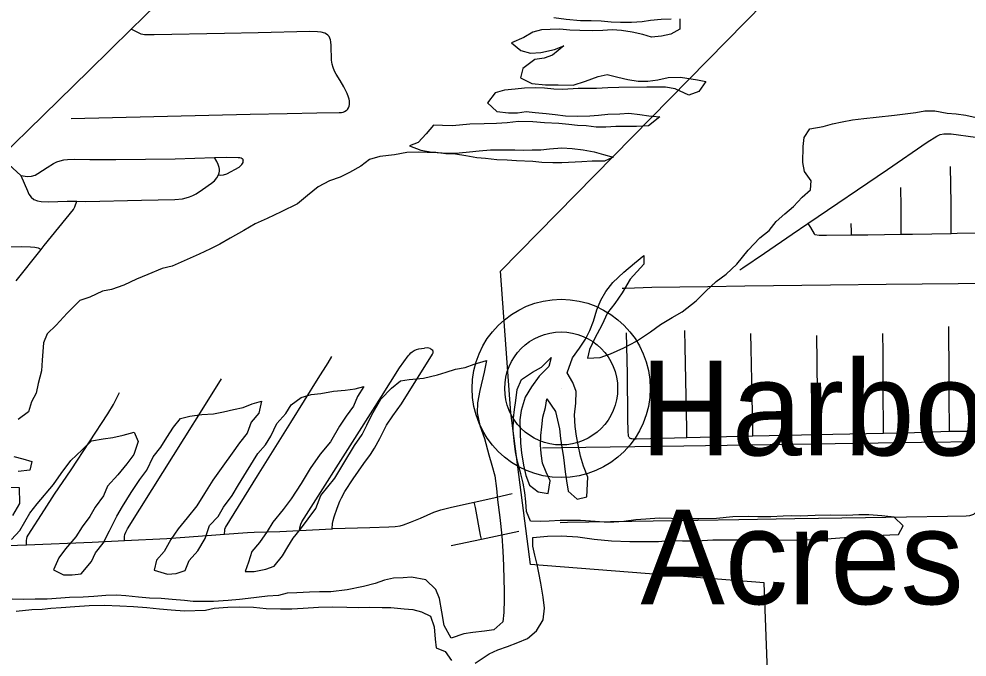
# Model space of a CAD drawing. Extents: x 0 to 34, y 0 to 22.
# Drawn here: x 6.2117 to 6.6076, y 19.4382 to 19.7044 of the extents above; entities that cross this region are included whole.
import ezdxf

# ---------------------------------------------------------------- set-up
doc = ezdxf.new("R2010")
doc.units = 0
for name, color, linetype in [('GM_X_Corporation', 7, 'Continuous'), ('GM_X_Minor_River', 7, 'Continuous'), ('GM_X_State_Route', 7, 'Continuous'), ('GM_X_Township_Road', 7, 'Continuous'), ('GM_X_Unincorporated', 7, 'Continuous'), ('GM_X_Unincorporated_Location', 7, 'Continuous'), ('GM_X_Unincorporated_Text', 7, 'Continuous')]:
    doc.layers.add(name, color=color, linetype=linetype)

msp = doc.modelspace()

# ---------------------------------------------------------------- linework, layer by layer
at = {"layer": 'GM_X_Corporation'}
msp.add_lwpolyline([(6.02093, 18.98289), (6.47248, 19.23007), (6.55287, 19.2304), (6.5506, 19.34193), (6.52687, 19.36184), (6.5229, 19.4692), (6.42525, 19.4768), (6.41702, 19.54004), (6.41272, 19.59919), (6.66443, 19.85526), (6.74265, 19.90025)], dxfattribs=at)
at = {"layer": 'GM_X_Minor_River'}
for points in [[(6.4876, 19.70455), (6.48762, 19.70018), (6.48384, 19.69807), (6.48004, 19.69729), (6.47587, 19.69689), (6.47226, 19.69801), (6.4677, 19.69894), (6.46333, 19.69968), (6.45934, 19.69985), (6.45554, 19.69965), (6.45118, 19.69943), (6.44586, 19.6996), (6.44169, 19.69977), (6.43751, 19.70013), (6.43352, 19.70011), (6.42992, 19.6999), (6.42631, 19.69894), (6.42253, 19.69664), (6.41741, 19.69452), (6.42123, 19.69131)], [(6.43501, 19.70506), (6.44014, 19.70433), (6.44622, 19.70379), (6.45059, 19.70381), (6.45476, 19.70363), (6.45894, 19.70327), (6.46293, 19.7031), (6.46749, 19.70312), (6.47185, 19.70334), (6.47546, 19.70392), (6.47982, 19.70432), (6.48399, 19.70453)], [(6.42123, 19.69131), (6.42522, 19.69019), (6.42959, 19.6904), (6.43527, 19.69175), (6.43925, 19.69329), (6.43453, 19.68928), (6.43093, 19.68812), (6.42713, 19.68753), (6.42203, 19.68371), (6.4211, 19.6799), (6.42586, 19.67745), (6.43155, 19.67691), (6.43687, 19.67693), (6.44313, 19.67677), (6.44825, 19.67851), (6.45356, 19.68043), (6.45735, 19.68121), (6.46172, 19.68009), (6.4659, 19.67916), (6.47027, 19.67842), (6.47426, 19.67844), (6.47843, 19.67903), (6.48279, 19.68), (6.48792, 19.68022), (6.49495, 19.67911), (6.49856, 19.67837), (6.49554, 19.67417), (6.49137, 19.67263), (6.48566, 19.67526), (6.48167, 19.676), (6.47807, 19.67599), (6.47389, 19.67597), (6.46212, 19.67591), (6.45757, 19.6757), (6.45282, 19.67549), (6.44523, 19.67545), (6.43878, 19.67504), (6.43498, 19.67521), (6.43118, 19.67557), (6.42738, 19.67575), (6.42283, 19.67553), (6.41884, 19.67514), (6.41448, 19.67473), (6.4105, 19.67357), (6.40729, 19.66938), (6.4113, 19.66578), (6.41605, 19.66523), (6.41984, 19.66525), (6.42345, 19.66584), (6.42725, 19.66548), (6.4318, 19.66493), (6.4356, 19.66457), (6.43997, 19.66402), (6.4451, 19.66385), (6.45003, 19.66407), (6.45364, 19.66427), (6.45762, 19.66467), (6.46256, 19.66489), (6.46635, 19.66509), (6.47091, 19.66454), (6.47471, 19.66399), (6.47927, 19.66363), (6.47454, 19.65981), (6.46961, 19.6596), (6.46088, 19.65955), (6.4567, 19.65934), (6.45272, 19.65932), (6.44854, 19.65988), (6.44493, 19.66005), (6.44132, 19.66041), (6.43714, 19.66077), (6.43107, 19.66112), (6.42632, 19.66148), (6.42024, 19.66164), (6.4155, 19.66105), (6.41113, 19.66084), (6.40601, 19.66062), (6.39994, 19.66059), (6.39273, 19.6598), (6.38855, 19.65997), (6.38475, 19.66014), (6.38173, 19.65652), (6.37834, 19.65289), (6.37473, 19.65154), (6.37949, 19.64966), (6.38424, 19.64892), (6.39051, 19.64838), (6.39544, 19.6486), (6.39981, 19.649), (6.40379, 19.6494), (6.40853, 19.6498), (6.41879, 19.64985), (6.42239, 19.64968), (6.426, 19.64988), (6.42961, 19.6499), (6.43321, 19.6503), (6.43833, 19.6507), (6.4427, 19.65034), (6.44726, 19.64979), (6.45182, 19.64905), (6.45581, 19.64793)], [(6.43001, 19.53431), (6.43037, 19.5383), (6.43149, 19.5423), (6.43204, 19.54592), (6.43568, 19.54061), (6.43742, 19.53339), (6.43782, 19.5294), (6.43841, 19.52579), (6.439, 19.52142), (6.43979, 19.51554), (6.44038, 19.51174), (6.44097, 19.50737), (6.44479, 19.50415), (6.44877, 19.50512), (6.44929, 19.5133), (6.44737, 19.51785), (6.44621, 19.52203), (6.44524, 19.52678), (6.44446, 19.53039), (6.44387, 19.53438), (6.44365, 19.53932), (6.4442, 19.54407), (6.44436, 19.54902), (6.44302, 19.55281), (6.44053, 19.55679), (6.44277, 19.56308), (6.44579, 19.56708), (6.44824, 19.5709), (6.45012, 19.57452), (6.45162, 19.57833), (6.45292, 19.58309), (6.45461, 19.58709), (6.45668, 19.59071), (6.4597, 19.59453), (6.46423, 19.59873), (6.46877, 19.60255), (6.47255, 19.6058), (6.47256, 19.60219), (6.4669, 19.59589), (6.46351, 19.59017), (6.4605, 19.58579), (6.45748, 19.58178), (6.45504, 19.57663), (6.45222, 19.5713), (6.44997, 19.56653), (6.44904, 19.56292), (6.45435, 19.56313), (6.45871, 19.56467), (6.4642, 19.56717), (6.4695, 19.57005), (6.47537, 19.57388), (6.47953, 19.57694), (6.48445, 19.57982), (6.48861, 19.58231), (6.49447, 19.5869), (6.49844, 19.59091), (6.50279, 19.59492), (6.50695, 19.59798), (6.51148, 19.60219), (6.5162, 19.60791), (6.5211, 19.61307), (6.52489, 19.61613), (6.5279, 19.61995), (6.53149, 19.6232), (6.53508, 19.62625), (6.53867, 19.63007), (6.54226, 19.63313), (6.54243, 19.63694), (6.53975, 19.64073), (6.53898, 19.64452), (6.53913, 19.65118), (6.53949, 19.65498), (6.54194, 19.65861), (6.54744, 19.65958), (6.55142, 19.66074), (6.5554, 19.66152), (6.55977, 19.6623), (6.56451, 19.6629), (6.56963, 19.66349), (6.57722, 19.66429), (6.58177, 19.66488), (6.58614, 19.66547), (6.58993, 19.66606), (6.59411, 19.66608), (6.59924, 19.66515), (6.60304, 19.66479), (6.60702, 19.66424), (6.61139, 19.66331)], [(6.45581, 19.64793), (6.4598, 19.64681), (6.45621, 19.64508), (6.45108, 19.64506), (6.44672, 19.64485), (6.43837, 19.64443), (6.43457, 19.64441), (6.43001, 19.64458), (6.42621, 19.64494), (6.41938, 19.64529), (6.41558, 19.64546), (6.41121, 19.64563), (6.40647, 19.64618), (6.40286, 19.64654), (6.3983, 19.64728), (6.39393, 19.64802), (6.38994, 19.64819), (6.38576, 19.64874), (6.38215, 19.64872), (6.37855, 19.6489), (6.37361, 19.64868), (6.36849, 19.64771), (6.36242, 19.64711), (6.35806, 19.64576), (6.35447, 19.64308), (6.34973, 19.64039), (6.34576, 19.63847), (6.3414, 19.63693), (6.33667, 19.63444), (6.33213, 19.6308), (6.32797, 19.62736), (6.32116, 19.62391), (6.31529, 19.62122), (6.31036, 19.61891), (6.30563, 19.61623), (6.29995, 19.61297), (6.2956, 19.61048), (6.29162, 19.60856), (6.28689, 19.60625), (6.28196, 19.60414), (6.27571, 19.60126), (6.27154, 19.60029), (6.26548, 19.59779), (6.26074, 19.59586), (6.25544, 19.59337), (6.25033, 19.59163), (6.24653, 19.59085), (6.24123, 19.58836), (6.23706, 19.587), (6.23177, 19.58166), (6.22724, 19.57669), (6.22347, 19.57306), (6.22197, 19.56925), (6.22161, 19.56564), (6.22143, 19.56203), (6.22108, 19.55765), (6.21978, 19.55232), (6.21885, 19.54833), (6.21697, 19.5447), (6.21566, 19.54052), (6.21131, 19.53726)], [(6.28639, 19.48249), (6.2894, 19.48764), (6.29127, 19.49316), (6.29486, 19.49679), (6.29711, 19.50079), (6.3007, 19.50556), (6.30333, 19.51013), (6.30672, 19.51547), (6.31143, 19.5231), (6.31463, 19.52673), (6.31689, 19.53035), (6.31933, 19.53568), (6.32311, 19.53989), (6.32537, 19.54351), (6.32953, 19.54657), (6.3337, 19.54773), (6.33768, 19.54813), (6.34299, 19.54911), (6.34793, 19.54951), (6.3521, 19.5501), (6.3557, 19.55107), (6.35307, 19.54687), (6.35138, 19.54287), (6.34836, 19.53867), (6.34554, 19.53448), (6.34177, 19.528), (6.33743, 19.52284), (6.33329, 19.51693), (6.32952, 19.51064), (6.32538, 19.50416), (6.32199, 19.49977), (6.31765, 19.49442), (6.31539, 19.49061), (6.31219, 19.48603), (6.30898, 19.48222), (6.30748, 19.47784), (6.30617, 19.47384), (6.30997, 19.47386), (6.31471, 19.47483), (6.31831, 19.47618), (6.32171, 19.48038), (6.32397, 19.48419), (6.32622, 19.48781), (6.32924, 19.49163), (6.33245, 19.49582), (6.33565, 19.50021), (6.33771, 19.50555), (6.34356, 19.5128), (6.34732, 19.51909), (6.35184, 19.52652), (6.35505, 19.5311), (6.35692, 19.53491), (6.35899, 19.5393), (6.36275, 19.54578), (6.36729, 19.55036), (6.37107, 19.55342), (6.37467, 19.55401), (6.38055, 19.55461), (6.38643, 19.55596), (6.39003, 19.55712), (6.39401, 19.55828), (6.39799, 19.55906), (6.40178, 19.56041), (6.4069, 19.56196), (6.40598, 19.55701), (6.40412, 19.5494), (6.40319, 19.54426), (6.40303, 19.54007), (6.40419, 19.53476), (6.40612, 19.52944), (6.40786, 19.52261), (6.40921, 19.51824), (6.41038, 19.51387), (6.41116, 19.50856), (6.41157, 19.5038), (6.41255, 19.49639), (6.41335, 19.4888), (6.41376, 19.48233), (6.41398, 19.47644), (6.41421, 19.47036), (6.41423, 19.46618), (6.41425, 19.46219), (6.41409, 19.45686), (6.41373, 19.45287), (6.40995, 19.44962), (6.40615, 19.44903), (6.40122, 19.44844), (6.39743, 19.44785), (6.39212, 19.44611), (6.38925, 19.45142), (6.38827, 19.45712), (6.38729, 19.46263), (6.38575, 19.46642), (6.38155, 19.47039), (6.37566, 19.47151), (6.37206, 19.4713), (6.36807, 19.47109), (6.36428, 19.47031), (6.36049, 19.46896), (6.35556, 19.46761), (6.34873, 19.46625)], [(6.42401, 19.44588), (6.42779, 19.44913), (6.43062, 19.45371), (6.43116, 19.45865), (6.43057, 19.46321), (6.42959, 19.4691), (6.42881, 19.47328), (6.42803, 19.47689), (6.42706, 19.48069), (6.42628, 19.48448), (6.42626, 19.4881), (6.43234, 19.4887), (6.43822, 19.48872), (6.44506, 19.48837), (6.45189, 19.48746), (6.45911, 19.48673), (6.46671, 19.48639), (6.47867, 19.48644), (6.48284, 19.48684), (6.48873, 19.48668), (6.4948, 19.48671), (6.50144, 19.48712), (6.51245, 19.48718), (6.51796, 19.48701), (6.53903, 19.48711), (6.54282, 19.48732), (6.54719, 19.48734), (6.5544, 19.48794), (6.56047, 19.48835), (6.56484, 19.48856), (6.56958, 19.48897), (6.57528, 19.48918), (6.57888, 19.48939), (6.58095, 19.49301), (6.57714, 19.49661), (6.57201, 19.49715), (6.5665, 19.49751), (6.56232, 19.49749), (6.55739, 19.49727), (6.55055, 19.49743), (6.5441, 19.49721), (6.53803, 19.49699), (6.53442, 19.49716), (6.53081, 19.49696), (6.52569, 19.49674), (6.52019, 19.49672), (6.5162, 19.49689), (6.50975, 19.49667), (6.50291, 19.49606), (6.49551, 19.49584), (6.48925, 19.49581), (6.479, 19.49614), (6.47349, 19.49573), (6.46932, 19.49553), (6.4642, 19.49474), (6.46002, 19.49453), (6.45603, 19.49451), (6.45034, 19.49486), (6.44616, 19.49522), (6.43762, 19.49518), (6.43306, 19.49497), (6.42927, 19.49476), (6.42528, 19.49494), (6.42355, 19.49892), (6.42334, 19.50291), (6.42294, 19.5069), (6.42216, 19.5107), (6.42119, 19.51469), (6.41984, 19.51981), (6.41906, 19.5238), (6.41846, 19.52836), (6.41806, 19.53254), (6.41822, 19.53787), (6.41859, 19.54148), (6.41914, 19.54528), (6.41968, 19.54985), (6.42156, 19.55404), (6.4261, 19.5571), (6.42988, 19.55921), (6.43385, 19.56322), (6.43292, 19.55942), (6.42895, 19.55541), (6.42575, 19.55102), (6.42311, 19.54663), (6.42143, 19.54111), (6.42089, 19.53712), (6.42091, 19.5318), (6.42113, 19.52742), (6.42153, 19.52343), (6.42231, 19.5183), (6.42328, 19.51394), (6.42482, 19.50995), (6.42844, 19.50712), (6.43262, 19.50638), (6.43355, 19.5117), (6.43182, 19.51531), (6.43028, 19.5191), (6.42969, 19.52309), (6.42948, 19.5267), (6.42965, 19.5307), (6.43001, 19.53431)], [(6.20853, 19.48725), (6.21212, 19.49107), (6.21419, 19.49469), (6.21626, 19.49831), (6.21928, 19.50213), (6.22607, 19.51015), (6.22927, 19.51473), (6.23342, 19.52026), (6.23814, 19.52465), (6.24192, 19.52847), (6.24685, 19.52926), (6.25083, 19.52985), (6.2552, 19.53082), (6.25975, 19.53198), (6.26147, 19.52819), (6.2596, 19.52266), (6.25678, 19.51885), (6.253, 19.51427), (6.24866, 19.50949), (6.24697, 19.50549), (6.24358, 19.50073), (6.24132, 19.49691), (6.23812, 19.49253), (6.23548, 19.48833), (6.23114, 19.48337), (6.22831, 19.47955), (6.22606, 19.4746), (6.23025, 19.47253), (6.23386, 19.47254), (6.23765, 19.47294), (6.24199, 19.4781), (6.24368, 19.48172), (6.24689, 19.48572), (6.24952, 19.49087), (6.25252, 19.49697), (6.25497, 19.50097), (6.25855, 19.50688), (6.26213, 19.51222), (6.26514, 19.51623), (6.26777, 19.52175), (6.27098, 19.52576), (6.27342, 19.52976), (6.27625, 19.53415), (6.27908, 19.53777), (6.28306, 19.53874), (6.28799, 19.53934), (6.29293, 19.53974), (6.2971, 19.54052), (6.30127, 19.54149), (6.30525, 19.54227), (6.30904, 19.54381), (6.31302, 19.54497), (6.31191, 19.54002), (6.3087, 19.5362), (6.30702, 19.53163), (6.30381, 19.52763), (6.30079, 19.52324), (6.29684, 19.5179), (6.29269, 19.51198), (6.28911, 19.50645), (6.28591, 19.50131), (6.28195, 19.49634), (6.27818, 19.49177), (6.27516, 19.48719), (6.27234, 19.48223), (6.26913, 19.47861), (6.2682, 19.47442), (6.27372, 19.47273), (6.27732, 19.47313), (6.28111, 19.47429), (6.2828, 19.47848), (6.28639, 19.48249)], [(6.20949, 19.52186), (6.21329, 19.52092), (6.2171, 19.5198), (6.21617, 19.51618), (6.21142, 19.51559)], [(6.20747, 19.50911), (6.21184, 19.50894), (6.21187, 19.50229), (6.20905, 19.49733)], [(6.34873, 19.46625), (6.34191, 19.46545), (6.33716, 19.46543), (6.33298, 19.46522), (6.32767, 19.46501), (6.32368, 19.4648), (6.32008, 19.46383), (6.31553, 19.46362), (6.30737, 19.46263), (6.30377, 19.46223), (6.29902, 19.46183), (6.29295, 19.46142), (6.28441, 19.46138), (6.2808, 19.46174), (6.27567, 19.46229), (6.27111, 19.46265), (6.26618, 19.46281), (6.26162, 19.46317), (6.2563, 19.46372), (6.2525, 19.46408), (6.24795, 19.46387), (6.24301, 19.46346), (6.23846, 19.46325), (6.23277, 19.46304), (6.22916, 19.46283), (6.22347, 19.46242), (6.21853, 19.4624), (6.21341, 19.46218), (6.20885, 19.46235)], [(6.21058, 19.45742), (6.21703, 19.45802), (6.2214, 19.45823), (6.225, 19.45863), (6.22937, 19.45884), (6.23506, 19.45924), (6.24095, 19.45965), (6.24721, 19.45987), (6.25385, 19.45952), (6.25955, 19.45936), (6.26506, 19.45882), (6.27038, 19.45827), (6.27531, 19.45791), (6.28082, 19.45756), (6.28955, 19.45779), (6.29315, 19.45857), (6.29885, 19.45898), (6.30378, 19.45919), (6.30967, 19.45903), (6.31498, 19.45848), (6.32087, 19.45832), (6.32562, 19.45834), (6.33036, 19.45855), (6.33681, 19.45897), (6.34251, 19.45918), (6.34858, 19.45902), (6.35333, 19.45885), (6.35807, 19.45907), (6.36339, 19.4589), (6.367, 19.45892), (6.3725, 19.45837), (6.37611, 19.45801), (6.37972, 19.45708), (6.38353, 19.4552), (6.38507, 19.45083), (6.38548, 19.4457), (6.38588, 19.44209), (6.38968, 19.44059), (6.39236, 19.4368)], [(6.40223, 19.43571), (6.4081, 19.43953), (6.4117, 19.44126), (6.41568, 19.44261), (6.42003, 19.44434), (6.42401, 19.44588)]]:
    msp.add_lwpolyline(points, dxfattribs=at)
at = {"layer": 'GM_X_State_Route'}
msp.add_lwpolyline([(6.20407, 19.64685), (6.2155, 19.65804), (6.24108, 19.683), (6.25859, 19.70013), (6.26884, 19.71017), (6.28115, 19.72204), (6.28876, 19.72983), (6.29297, 19.73443), (6.29696, 19.73923), (6.29716, 19.73951), (6.29975, 19.74299), (6.30411, 19.74945), (6.30473, 19.75045), (6.3082, 19.75608), (6.32754, 19.78977), (6.33927, 19.80955), (6.34022, 19.81115), (6.34149, 19.81326), (6.34272, 19.8153), (6.36583, 19.85377), (6.38322, 19.88321)], dxfattribs=at)
at = {"layer": 'GM_X_Township_Road'}
for p, q in [((6.51811, 19.53048), (6.54532, 19.5311)), ((6.32884, 19.49103), (6.34241, 19.49177)), ((6.40478, 19.48739), (6.42036, 19.49069)), ((6.39214, 19.48471), (6.40478, 19.48739))]:
    msp.add_line(p, q, dxfattribs=at)
for points in [[(6.23356, 19.66294), (6.30822, 19.66471), (6.32373, 19.66497), (6.33613, 19.66533), (6.34546, 19.66541), (6.34631, 19.66545), (6.34701, 19.6656), (6.34759, 19.6658), (6.34836, 19.66619), (6.34861, 19.66638), (6.34892, 19.66668), (6.34931, 19.66731), (6.34958, 19.66799), (6.34975, 19.66877), (6.34978, 19.66964), (6.34972, 19.67033), (6.34956, 19.67097), (6.34931, 19.67184), (6.34873, 19.67328), (6.34735, 19.67607), (6.34579, 19.67872), (6.34413, 19.68134), (6.3434, 19.6827), (6.34284, 19.68415), (6.34245, 19.68564), (6.34225, 19.68718), (6.34205, 19.69339), (6.34191, 19.69495), (6.34177, 19.69569), (6.34151, 19.69644), (6.34118, 19.69706), (6.34064, 19.69769), (6.34015, 19.69805), (6.33937, 19.69848), (6.33788, 19.69888), (6.33633, 19.6991), (6.33322, 19.69922), (6.31151, 19.69869), (6.29756, 19.69844), (6.26809, 19.69788), (6.26609, 19.69781), (6.26417, 19.69782), (6.26343, 19.69793), (6.26269, 19.69816), (6.26128, 19.69884), (6.25859, 19.70013)], [(6.54113, 19.61905), (6.57434, 19.64161), (6.59096, 19.65306), (6.59491, 19.65554), (6.59631, 19.65618), (6.59781, 19.65652), (6.59935, 19.65658), (6.6009, 19.65646), (6.63147, 19.65235), (6.63466, 19.65192)], [(6.20407, 19.64685), (6.2075, 19.64374), (6.21253, 19.63915)], [(6.2933, 19.6466), (6.29854, 19.64675), (6.30318, 19.6467), (6.30392, 19.64662), (6.30445, 19.64643), (6.30484, 19.64623), (6.30516, 19.64593), (6.30533, 19.64548)], [(6.21253, 19.63915), (6.21529, 19.63875), (6.21695, 19.63885), (6.21848, 19.63929), (6.21955, 19.63993), (6.22345, 19.64246), (6.2261, 19.64408), (6.22749, 19.64476), (6.22894, 19.64527), (6.23044, 19.64562), (6.23198, 19.64581), (6.23508, 19.64592), (6.24127, 19.64575), (6.2521, 19.64586), (6.27687, 19.64611), (6.2933, 19.6466)], [(6.29506, 19.63943), (6.29529, 19.64022), (6.29537, 19.64096), (6.29539, 19.64183), (6.29526, 19.64253), (6.2949, 19.64373), (6.29437, 19.6449), (6.2933, 19.6466)], [(6.29506, 19.63943), (6.29593, 19.63925), (6.29714, 19.63934), (6.29843, 19.6398), (6.30359, 19.64264), (6.30433, 19.64324), (6.30479, 19.64378), (6.30509, 19.64415), (6.30528, 19.64461), (6.30534, 19.64505), (6.30533, 19.64548)], [(6.60092, 19.61498), (6.60092, 19.61817), (6.60092, 19.62742), (6.60059, 19.64283)], [(6.21253, 19.63915), (6.21522, 19.63271), (6.21584, 19.63128), (6.21675, 19.63003), (6.21796, 19.62912), (6.21938, 19.62856), (6.22091, 19.62829), (6.22404, 19.62819), (6.2318, 19.62839), (6.23582, 19.62837)], [(6.23582, 19.62837), (6.23956, 19.62834), (6.26286, 19.62888), (6.27683, 19.62914), (6.27992, 19.62946), (6.28145, 19.62976), (6.28293, 19.6302), (6.28436, 19.63079), (6.28572, 19.63151), (6.28831, 19.63323), (6.2921, 19.63597), (6.29334, 19.63697), (6.29435, 19.63811), (6.29506, 19.63943)], [(6.58007, 19.61463), (6.58005, 19.61795), (6.58, 19.62602), (6.57985, 19.63409)], [(6.22093, 19.60821), (6.22226, 19.60988), (6.23444, 19.62488), (6.23508, 19.62608), (6.23582, 19.62837)], [(6.51267, 19.59983), (6.51397, 19.60067), (6.52297, 19.60676), (6.53454, 19.61458), (6.54113, 19.61905)], [(6.54113, 19.61905), (6.54214, 19.61739), (6.54376, 19.61472), (6.54402, 19.61455), (6.54585, 19.61418), (6.54893, 19.61429), (6.55927, 19.61438)], [(6.55927, 19.61438), (6.55927, 19.61569), (6.55925, 19.61908)], [(6.58007, 19.61463), (6.58475, 19.6147), (6.60092, 19.61498)], [(6.60092, 19.61498), (6.60341, 19.61502), (6.62176, 19.61521)], [(6.55927, 19.61438), (6.56608, 19.61443), (6.58007, 19.61463)], [(6.18373, 19.6085), (6.18666, 19.60867), (6.19593, 19.6091), (6.21289, 19.60947), (6.21656, 19.60939), (6.21836, 19.60922), (6.21978, 19.60893), (6.22093, 19.60821)], [(6.21054, 19.5952), (6.22093, 19.60821)], [(6.46359, 19.59205), (6.46514, 19.59213), (6.47601, 19.5925), (6.49929, 19.59283), (6.51481, 19.59306), (6.55052, 19.59354), (6.57381, 19.59378), (6.61883, 19.59417), (6.62193, 19.59426), (6.62347, 19.59442), (6.62499, 19.59472), (6.62649, 19.59513), (6.62795, 19.59565), (6.62936, 19.5963), (6.6307, 19.59707), (6.63242, 19.59833)], [(6.60028, 19.53239), (6.60024, 19.53521), (6.60013, 19.54464), (6.60012, 19.56194), (6.60002, 19.5698), (6.59996, 19.57451), (6.59992, 19.57607)], [(6.46652, 19.5298), (6.46623, 19.53033), (6.46614, 19.53072), (6.46613, 19.53214), (6.46597, 19.53787), (6.46576, 19.55644), (6.46531, 19.57347)], [(6.49063, 19.52979), (6.49055, 19.53344), (6.49013, 19.55369), (6.48983, 19.56772), (6.48976, 19.57445)], [(6.51811, 19.53048), (6.51807, 19.5329), (6.51786, 19.54685), (6.51741, 19.567), (6.51727, 19.5732)], [(6.54532, 19.5311), (6.54527, 19.53459), (6.54492, 19.56138), (6.54485, 19.57241)], [(6.57269, 19.53165), (6.57268, 19.5342), (6.5726, 19.54823), (6.57251, 19.56539), (6.5724, 19.57319)], [(6.29752, 19.48948), (6.29762, 19.49114), (6.2977, 19.49163), (6.29792, 19.49229), (6.31127, 19.51386), (6.32527, 19.53605), (6.3367, 19.55438), (6.34078, 19.56092), (6.3423, 19.56361)], [(6.32884, 19.49103), (6.32901, 19.49206), (6.32939, 19.49359), (6.32977, 19.49458), (6.35389, 19.53242), (6.36312, 19.54691), (6.37066, 19.55882), (6.37419, 19.56395), (6.3747, 19.56451), (6.37526, 19.56507), (6.37592, 19.5656), (6.37675, 19.5661), (6.3777, 19.56648), (6.37868, 19.56675), (6.3798, 19.56697), (6.38101, 19.56712)], [(6.34241, 19.49177), (6.34262, 19.49394), (6.34286, 19.49519), (6.34328, 19.49669), (6.34458, 19.50029), (6.34567, 19.50321), (6.34631, 19.50462), (6.34782, 19.50733), (6.35119, 19.51257), (6.3557, 19.51892), (6.35845, 19.5227), (6.36013, 19.52531), (6.36238, 19.52939), (6.3644, 19.5336), (6.36515, 19.53496), (6.36777, 19.53882), (6.37149, 19.54381), (6.38434, 19.56456), (6.38461, 19.56508), (6.38469, 19.56539), (6.38467, 19.56574), (6.38452, 19.56605), (6.38405, 19.56644), (6.38363, 19.56673), (6.38335, 19.56689), (6.3829, 19.56711), (6.38234, 19.56721), (6.38101, 19.56712)], [(6.25573, 19.48684), (6.25576, 19.48857), (6.25588, 19.48929), (6.2563, 19.4903), (6.25695, 19.49165), (6.26733, 19.50809), (6.28071, 19.52943), (6.28891, 19.54246), (6.29621, 19.55426)], [(6.21487, 19.48507), (6.21488, 19.48683), (6.21495, 19.48763), (6.21518, 19.48836), (6.21554, 19.48908), (6.22235, 19.49963), (6.22655, 19.50612), (6.23351, 19.51635), (6.24878, 19.53965), (6.25117, 19.54363), (6.25373, 19.54859)], [(6.57269, 19.53165), (6.58566, 19.5319), (6.60028, 19.53239)], [(6.60028, 19.53239), (6.60276, 19.53248), (6.60901, 19.53242), (6.61058, 19.53233), (6.61369, 19.53185), (6.61574, 19.53144)], [(6.43032, 19.52544), (6.43807, 19.52559), (6.48926, 19.52627), (6.58852, 19.52781), (6.61285, 19.52819), (6.61374, 19.5282)], [(6.43762, 19.49437), (6.44073, 19.49448), (6.47649, 19.49505), (6.49515, 19.49526), (6.51227, 19.49554), (6.53559, 19.49596), (6.56514, 19.49646), (6.59935, 19.49693), (6.60717, 19.49708), (6.60878, 19.4973), (6.61036, 19.49785), (6.61171, 19.49888), (6.61264, 19.50029), (6.61312, 19.50185), (6.61329, 19.50347), (6.61328, 19.50507), (6.61255, 19.52064), (6.61251, 19.52372), (6.61266, 19.52521), (6.61304, 19.5266), (6.61353, 19.52786), (6.61374, 19.5282)], [(6.46652, 19.5298), (6.46686, 19.52953), (6.46722, 19.5294), (6.46761, 19.52933), (6.46809, 19.52931), (6.4694, 19.5293), (6.4753, 19.52936), (6.49063, 19.52979)], [(6.49063, 19.52979), (6.50172, 19.53011), (6.51811, 19.53048)], [(6.54532, 19.5311), (6.55147, 19.53124), (6.57269, 19.53165)], [(6.40182, 19.50287), (6.4087, 19.50439), (6.41767, 19.50642)], [(6.37931, 19.49619), (6.38494, 19.49861), (6.38785, 19.4996), (6.39229, 19.50076), (6.40182, 19.50287)], [(6.40478, 19.48739), (6.40446, 19.48909), (6.40226, 19.5006), (6.40182, 19.50287)], [(6.34241, 19.49177), (6.34279, 19.49179), (6.35815, 19.49224), (6.36615, 19.4925), (6.36872, 19.49269), (6.3709, 19.49301), (6.37222, 19.49336), (6.37514, 19.49443), (6.37931, 19.49619)], [(6.25573, 19.48684), (6.27345, 19.4877), (6.29212, 19.4891), (6.29752, 19.48948)], [(6.29752, 19.48948), (6.30713, 19.49016), (6.3099, 19.49029)], [(6.3099, 19.49029), (6.32057, 19.49064), (6.32884, 19.49103)], [(6.12065, 19.48246), (6.1488, 19.4832), (6.19243, 19.48445), (6.21114, 19.48492), (6.21487, 19.48507)], [(6.21487, 19.48507), (6.2423, 19.4862), (6.25573, 19.48684)]]:
    msp.add_lwpolyline(points, dxfattribs=at)
at = {"layer": 'GM_X_Unincorporated'}
for radius in [0.0372, 0.02358]:
    msp.add_circle((6.4381, 19.55027), radius, dxfattribs=at)
at = {"layer": 'GM_X_Unincorporated_Location'}
msp.add_line((6.4381, 19.55027), (6.4381, 19.55027), dxfattribs=at)

# ---------------------------------------------------------------- texts
at = {"layer": 'GM_X_Unincorporated_Text'}
for s, p in [('Harbor', (6.4712, 19.52234)), ('Acres', (6.4712, 19.46026))]:
    msp.add_text(s, height=0.039489, rotation=0, dxfattribs=at).set_placement(p)

doc.saveas('drawing.dxf')
